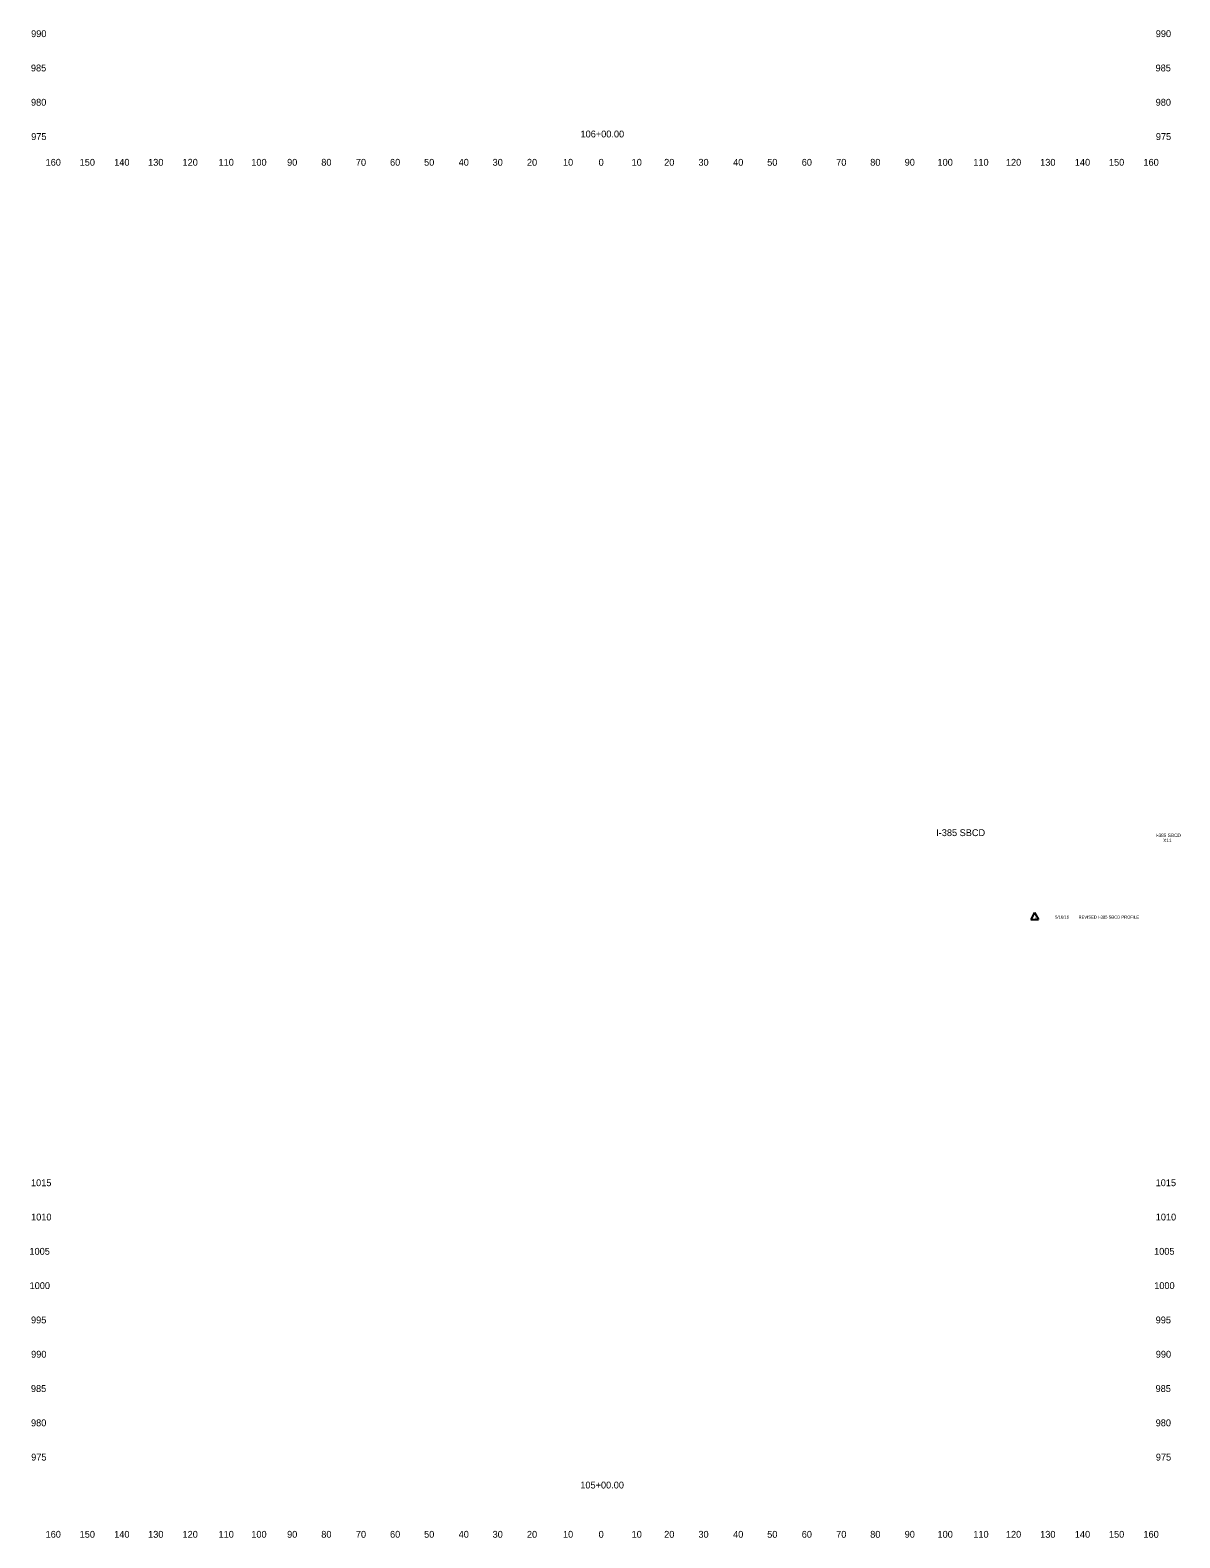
# Model space of a CAD drawing. Extents: x 4994 to 6876, y 4997 to 8804.
# Drawn here: x 5508.6 to 5843.7, y 4997.5 to 5437 of the extents above; entities that cross this region are included whole.
import ezdxf

# ---------------------------------------------------------------- set-up
doc = ezdxf.new("R2010")
doc.units = 0
for name, color, linetype in [('RD_SHT_ID', 7, 'Continuous'), ('RD_SHT_TX', 7, 'Continuous'), ('RD_XS_TX_Offset', 7, 'Continuous'), ('RD_XS_TX_Station', 7, 'Continuous')]:
    doc.layers.add(name, color=color, linetype=linetype)

msp = doc.modelspace()

# ---------------------------------------------------------------- linework, layer by layer
at = {"layer": 'RD_SHT_TX'}
for p, q in [((5801.37, 5179.75), (5800.23, 5177.72)), ((5801.37, 5179.75), (5802.51, 5177.72)), ((5800.23, 5177.72), (5802.51, 5177.72))]:
    msp.add_line(p, q, dxfattribs=at)

# ---------------------------------------------------------------- texts
at = {"layer": 'RD_SHT_ID'}
for s, height, p in [('I-385 SBCD', 2, (5772.69, 5202.06)), ('I-385 SBCD', 1, (5836.63, 5201.8)), ('X11', 1, (5838.85, 5200.3))]:
    msp.add_text(s, height=height, dxfattribs=at).set_placement(p)
at = {"layer": 'RD_SHT_TX'}
for s, p in [('1', (5801.37, 5178.05)), ('5/16/16', (5807.34, 5178.01)), ('REVISED I-385 SBCD PROFILE', (5814.17, 5178.01))]:
    msp.add_text(s, height=0.88, dxfattribs=at).set_placement(p)
at = {"layer": 'RD_XS_TX_Offset'}
for s, p in [('990', (5508.89, 5435)), ('990', (5836.69, 5435)), ('985', (5508.83, 5425)), ('985', (5836.63, 5425)), ('980', (5508.86, 5415)), ('980', (5836.66, 5415)), ('975', (5508.91, 5405)), ('975', (5836.71, 5405)), ('160', (5513.1, 5397.5)), ('150', (5523.04, 5397.5)), ('140', (5533.1, 5397.5)), ('130', (5542.99, 5397.5)), ('120', (5553.01, 5397.5)), ('110', (5563.51, 5397.5)), ('100', (5573.07, 5397.5)), ('90', (5583.5, 5397.5)), ('80', (5593.46, 5397.5)), ('70', (5603.54, 5397.5)), ('60', (5613.5, 5397.5)), ('50', (5623.43, 5397.5)), ('40', (5633.5, 5397.5)), ('30', (5643.39, 5397.5)), ('20', (5653.4, 5397.5)), ('10', (5663.91, 5397.5)), ('0', (5674.3, 5397.5)), ('0', (5674.3, 5397.5)), ('10', (5683.91, 5397.5)), ('20', (5693.4, 5397.5)), ('30', (5703.39, 5397.5)), ('40', (5713.5, 5397.5)), ('50', (5723.43, 5397.5)), ('60', (5733.5, 5397.5)), ('70', (5743.54, 5397.5)), ('80', (5753.46, 5397.5)), ('90', (5763.5, 5397.5)), ('100', (5773.07, 5397.5)), ('110', (5783.51, 5397.5)), ('120', (5793.01, 5397.5)), ('130', (5802.99, 5397.5)), ('140', (5813.1, 5397.5)), ('150', (5823.04, 5397.5)), ('160', (5833.1, 5397.5)), ('1015', (5508.85, 5100)), ('1015', (5836.65, 5100)), ('1010', (5508.88, 5090)), ('1010', (5836.68, 5090)), ('1005', (5508.4, 5080)), ('1005', (5836.2, 5080)), ('1000', (5508.44, 5070)), ('1000', (5836.24, 5070)), ('995', (5508.86, 5060)), ('995', (5836.66, 5060)), ('990', (5508.89, 5050)), ('990', (5836.69, 5050)), ('985', (5508.83, 5040)), ('985', (5836.63, 5040)), ('980', (5508.86, 5030)), ('980', (5836.66, 5030)), ('975', (5508.91, 5020)), ('975', (5836.71, 5020)), ('160', (5513.1, 4997.5)), ('150', (5523.04, 4997.5)), ('140', (5533.1, 4997.5)), ('130', (5542.99, 4997.5)), ('120', (5553.01, 4997.5)), ('110', (5563.51, 4997.5)), ('100', (5573.07, 4997.5)), ('90', (5583.5, 4997.5)), ('80', (5593.46, 4997.5)), ('70', (5603.54, 4997.5)), ('60', (5613.5, 4997.5)), ('50', (5623.43, 4997.5)), ('40', (5633.5, 4997.5)), ('30', (5643.39, 4997.5)), ('20', (5653.4, 4997.5)), ('10', (5663.91, 4997.5)), ('0', (5674.3, 4997.5)), ('0', (5674.3, 4997.5)), ('10', (5683.91, 4997.5)), ('20', (5693.4, 4997.5)), ('30', (5703.39, 4997.5)), ('40', (5713.5, 4997.5)), ('50', (5723.43, 4997.5)), ('60', (5733.5, 4997.5)), ('70', (5743.54, 4997.5)), ('80', (5753.46, 4997.5)), ('90', (5763.5, 4997.5)), ('100', (5773.07, 4997.5)), ('110', (5783.51, 4997.5)), ('120', (5793.01, 4997.5)), ('130', (5802.99, 4997.5)), ('140', (5813.1, 4997.5)), ('150', (5823.04, 4997.5)), ('160', (5833.1, 4997.5))]:
    msp.add_text(s, height=2, dxfattribs=at).set_placement(p)
at = {"layer": 'RD_XS_TX_Station'}
for s, p in [('106+00.00', (5669.02, 5405.75)), ('105+00.00', (5668.96, 5011.86))]:
    msp.add_text(s, height=2, dxfattribs=at).set_placement(p)

doc.saveas('drawing.dxf')
